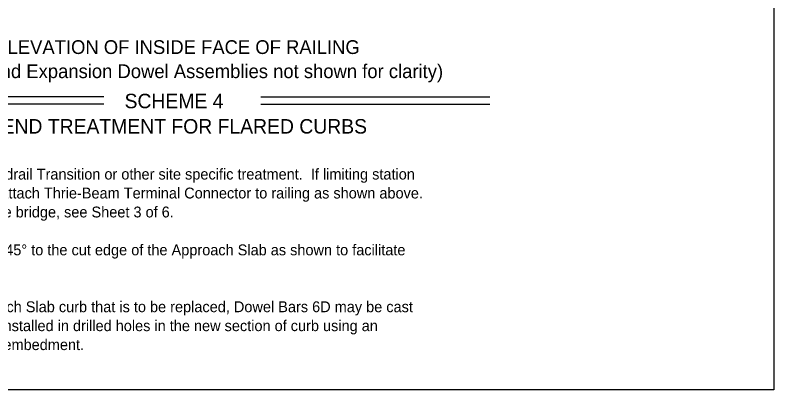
# Model space of a CAD drawing. Extents: x 1.5 to 68.7, y 0 to 31.1.
# Drawn here: x 28.44 to 42.53, y 1.78 to 8.74 of the extents above; entities that cross this region are included whole.
import ezdxf

# ---------------------------------------------------------------- set-up
doc = ezdxf.new("R2010")
doc.units = 0
doc.layers.add('ActivePts-ConstElements', color=7, linetype='Continuous')
doc.layers.add('AdhocPoint_dp', color=7, linetype='Continuous')

msp = doc.modelspace()

# ---------------------------------------------------------------- linework, layer by layer
at = {"layer": 'ActivePts-ConstElements'}
msp.add_lwpolyline([(1.467, 28.183), (42.533, 28.183), (42.533, 1.783), (1.467, 1.783)], close=True, dxfattribs=at)
at = {"layer": 'AdhocPoint_dp'}
for p, q in [((30.085, 7.224), (25.826, 7.224)), ((33, 7.224), (37.259, 7.224)), ((30.085, 7.091), (25.826, 7.091)), ((33, 7.091), (37.259, 7.091))]:
    msp.add_line(p, q, dxfattribs=at)

# ---------------------------------------------------------------- texts
for s, height, p in [('PARTIAL ELEVATION OF INSIDE FACE OF RAILING', 0.256, (26.546, 8.021)), ('(Existing Wing Post, Railing Reinforcing and Expansion Dowel Assemblies not shown for clarity)', 0.256, (21.852, 7.573)), ('SCHEME 4', 0.2688, (30.47, 7.013)), ('RAILING END TREATMENT FOR FLARED CURBS', 0.2688, (26.647, 6.543)), ('1. See Roadway Plans for limiting station of Roadway Guardrail Transition or other site specific treatment.  If limiting station ', 0.2016, (21.18, 5.689)), ('   of Roadway Guardrail Transition is along the Wing Wall, attach Thrie-Beam Terminal Connector to railing as shown above.  ', 0.2016, (21.18, 5.337)), ('   If limiting station of Roadway Guardrail Transition is on the bridge, see Sheet 3 of 6.', 0.2016, (21.18, 4.985)), ('2. Dowel Bars 4N may be installed on a maximum angle of 45° to the cut edge of the Approach Slab as shown to facilitate ', 0.2016, (21.18, 4.281)), ("3. At the Contractor's option, along the length of the Approach Slab curb that is to be replaced, Dowel Bars 6D may be cast ", 0.2016, (21.18, 3.225)), ('   in with the new section of curb as shown or they may be installed in drilled holes in the new section of curb using an ', 0.2016, (21.18, 2.873)), ('   Adhesive Bonding Material System with a 1\'-0" minimum embedment. ', 0.2016, (21.18, 2.521))]:
    msp.add_text(s, height=height, dxfattribs=at).set_placement(p)

doc.saveas('drawing.dxf')
